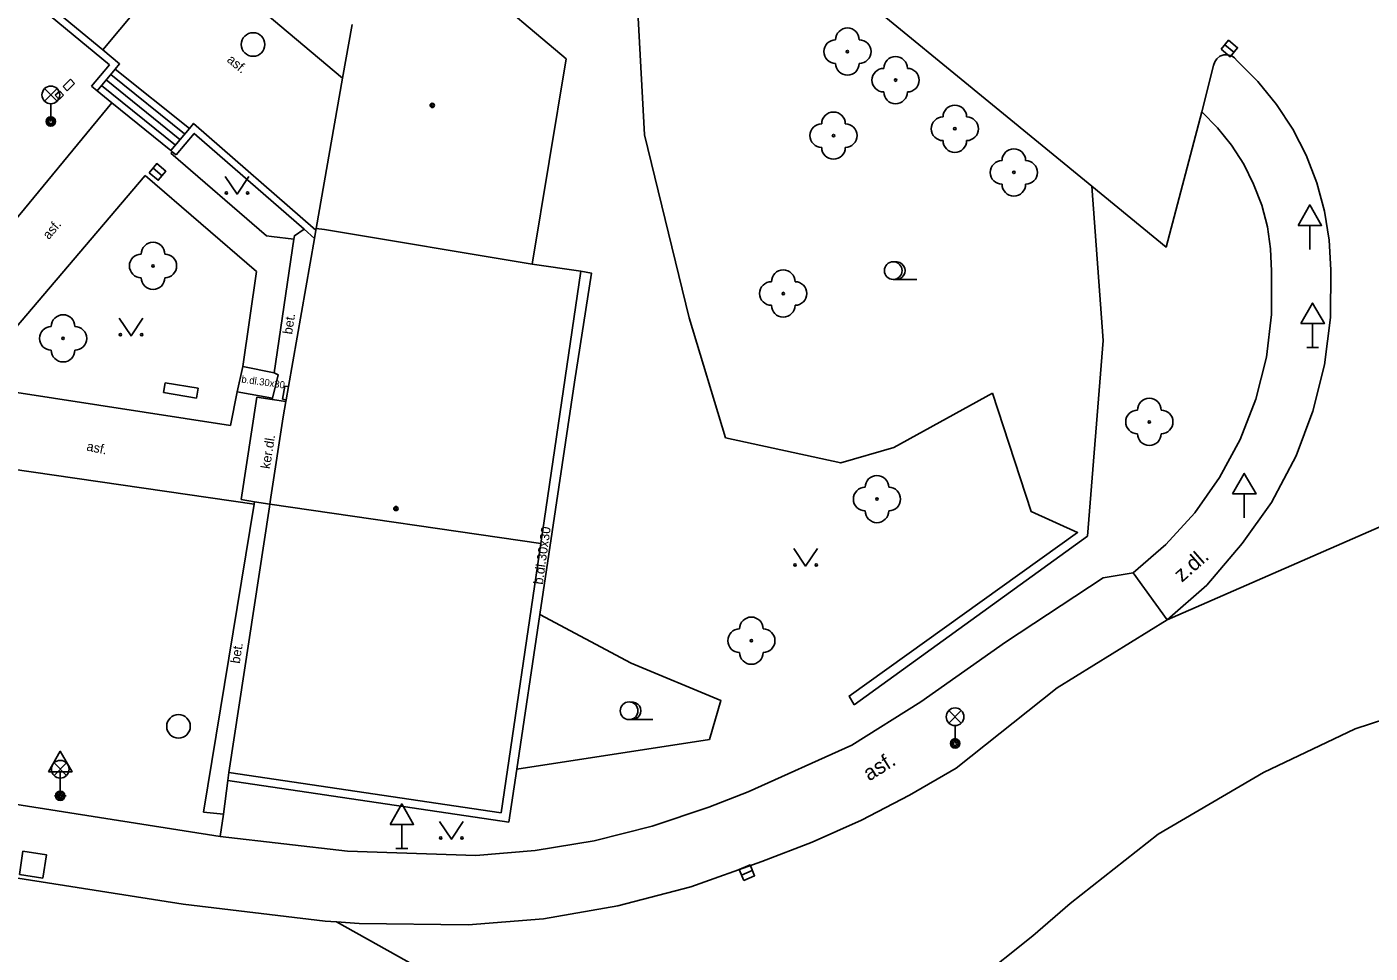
# Model space of a CAD drawing. Extents: x -598932 to -598196, y -1162207 to -1161504.
# Drawn here: x -598441.5 to -598384.6, y -1162005.3 to -1161966.1 of the extents above; entities that cross this region are included whole.
import ezdxf

# ---------------------------------------------------------------- set-up
doc = ezdxf.new("R2010")
doc.units = 0
for name, color, linetype in [('Level 22', 7, 'Continuous'), ('Level 26', 7, 'Continuous'), ('Level 27', 7, 'Continuous'), ('Level 33', 7, 'Continuous'), ('Level 34', 7, 'Continuous'), ('Level 36', 7, 'Continuous'), ('Level 39', 7, 'Continuous'), ('silnoproud - povrch.  znaky a  RIS  skut. velikost', 7, 'Continuous'), ('specificka linie pasportu komunikaci', 7, 'Continuous'), ('TM - budovy zdene_ betonove - NP', 7, 'Continuous'), ('TM - budovy zdene_ betonove - VN', 7, 'Continuous'), ('TM - budovy zdene_ betonove - VP', 7, 'Continuous'), ('TM - chodniky - VP', 7, 'Continuous'), ('TM - hranice souvisleho porostu (skupiny stromu_ kere)', 7, 'Continuous'), ('TM - komunikace - VP', 7, 'Continuous'), ('TM - letecke snimky - pomocna linie', 7, 'Continuous'), ('TM - podezdivka plotu - VP', 7, 'Continuous'), ('TM - pomocna konstrukcna linie', 7, 'Continuous'), ('TM - popis povrchu', 7, 'Continuous'), ('TM - rozhrani mezi zpev. plochami mezi sebou - VP', 7, 'Continuous'), ('TM - rozhrani ploch obecne - VP', 7, 'Continuous'), ('TM - schody - VP', 7, 'Continuous'), ('TM - vstup do budovy - nerozlisene', 7, 'Continuous'), ('TM - zed operna - VP', 7, 'Continuous')]:
    doc.layers.add(name, color=color, linetype=linetype)

msp = doc.modelspace()

# ---------------------------------------------------------------- linework, layer by layer
at = {"layer": 'Level 22'}
for centre in [(-598406.76, -1161967.12), (-598404.72, -1161968.33), (-598407.35, -1161970.68), (-598402.21, -1161970.39), (-598399.71, -1161972.24), (-598436.18, -1161976.2), (-598409.48, -1161977.37), (-598439.99, -1161979.27), (-598393.97, -1161982.81), (-598405.51, -1161986.08), (-598410.83, -1161992.08)]:
    msp.add_circle(centre, 0.05, dxfattribs=at)
for centre, start, end in [((-598406.76, -1161966.62), 0, 180), ((-598407.26, -1161967.12), 90, 270), ((-598406.26, -1161967.12), 270, 90), ((-598406.76, -1161967.62), 180, 0), ((-598405.22, -1161968.33), 90, 270), ((-598404.72, -1161967.83), 0, 180), ((-598404.22, -1161968.33), 270, 90), ((-598404.72, -1161968.83), 180, 0), ((-598402.21, -1161969.89), 0, 180), ((-598407.35, -1161970.18), 0, 180), ((-598402.71, -1161970.39), 90, 270), ((-598401.71, -1161970.39), 270, 90), ((-598407.85, -1161970.68), 90, 270), ((-598406.85, -1161970.68), 270, 90), ((-598407.35, -1161971.18), 180, 0), ((-598402.21, -1161970.89), 180, 0), ((-598399.71, -1161971.74), 0, 180), ((-598400.21, -1161972.24), 90, 270), ((-598399.21, -1161972.24), 270, 90), ((-598399.71, -1161972.74), 180, 0), ((-598436.18, -1161975.7), 0, 180), ((-598436.68, -1161976.2), 90, 270), ((-598435.68, -1161976.2), 270, 90), ((-598409.48, -1161976.87), 0, 180), ((-598436.18, -1161976.7), 180, 0), ((-598409.98, -1161977.37), 90, 270), ((-598408.98, -1161977.37), 270, 90), ((-598409.48, -1161977.87), 180, 0), ((-598439.99, -1161978.77), 0, 180), ((-598440.49, -1161979.27), 90, 270), ((-598439.49, -1161979.27), 270, 90), ((-598439.99, -1161979.77), 180, 0), ((-598393.97, -1161982.31), 0, 180), ((-598394.47, -1161982.81), 90, 270), ((-598393.47, -1161982.81), 270, 90), ((-598393.97, -1161983.31), 180, 0), ((-598405.51, -1161985.58), 0, 180), ((-598406.01, -1161986.08), 90, 270), ((-598405.01, -1161986.08), 270, 90), ((-598405.51, -1161986.58), 180, 0), ((-598410.83, -1161991.58), 0, 180), ((-598411.33, -1161992.08), 90, 270), ((-598410.33, -1161992.08), 270, 90), ((-598410.83, -1161992.58), 180, 0)]:
    msp.add_arc(centre, 0.5, start, end, dxfattribs=at)
at = {"layer": 'Level 26'}
msp.add_lwpolyline([(-598441.84, -1162001.989), (-598440.851, -1162002.14), (-598440.7, -1162001.151), (-598441.689, -1162001)], close=True, dxfattribs=at)
at = {"layer": 'Level 27'}
for p, q in [((-598390.773, -1161966.831), (-598390.387, -1161967.149)), ((-598436.181, -1161972.059), (-598435.799, -1161972.381)), ((-598411.25, -1162002.008), (-598410.79, -1162001.812))]:
    msp.add_line(p, q, dxfattribs=at)
for points in [[(-598390.932, -1161967.023), (-598390.547, -1161967.342), (-598390.228, -1161966.957), (-598390.613, -1161966.638)], [(-598436.342, -1161972.251), (-598435.959, -1161972.572), (-598435.638, -1161972.189), (-598436.021, -1161971.868)], [(-598411.152, -1162002.238), (-598410.692, -1162002.042), (-598410.888, -1162001.582), (-598411.348, -1162001.778)]]:
    msp.add_lwpolyline(points, close=True, dxfattribs=at)
for centre in [(-598431.94, -1161966.82), (-598435.1, -1161995.71)]:
    msp.add_circle(centre, 0.5, dxfattribs=at)
at = {"layer": 'Level 33'}
for p, q in [((-598440.775, -1161969.22), (-598440.245, -1161968.69)), ((-598440.775, -1161968.69), (-598440.245, -1161969.22)), ((-598440.51, -1161969.33), (-598440.51, -1161970.08)), ((-598402.465, -1161995.57), (-598401.935, -1161995.04)), ((-598402.465, -1161995.04), (-598401.935, -1161995.57)), ((-598402.2, -1161995.68), (-598402.2, -1161996.43)), ((-598440.375, -1161997.79), (-598439.845, -1161997.26)), ((-598440.375, -1161997.26), (-598439.845, -1161997.79)), ((-598440.11, -1161997.9), (-598440.11, -1161998.65))]:
    msp.add_line(p, q, dxfattribs=at)
for centre, radius in [((-598440.51, -1161968.955), 0.375), ((-598440.51, -1161970.08), 0.2), ((-598440.51, -1161970.08), 0.145), ((-598440.51, -1161970.08), 0.0876), ((-598402.2, -1161995.305), 0.375), ((-598402.2, -1161996.43), 0.2), ((-598402.2, -1161996.43), 0.145), ((-598402.2, -1161996.43), 0.0876), ((-598440.11, -1161997.525), 0.375), ((-598440.11, -1161998.65), 0.2), ((-598440.11, -1161998.65), 0.145), ((-598440.11, -1161998.65), 0.0876)]:
    msp.add_circle(centre, radius, dxfattribs=at)
at = {"layer": 'Level 34'}
for p, q in [((-598387.17, -1161974.482), (-598387.17, -1161975.5)), ((-598387.05, -1161978.642), (-598387.05, -1161979.66)), ((-598387.3, -1161979.66), (-598386.8, -1161979.66)), ((-598389.95, -1161985.862), (-598389.95, -1161986.88)), ((-598440.11, -1161997.632), (-598440.11, -1161998.65)), ((-598440.36, -1161998.65), (-598439.86, -1161998.65)), ((-598425.64, -1161999.862), (-598425.64, -1162000.88)), ((-598425.89, -1162000.88), (-598425.39, -1162000.88))]:
    msp.add_line(p, q, dxfattribs=at)
for points in [[(-598387.67, -1161974.482), (-598386.67, -1161974.482), (-598387.17, -1161973.616)], [(-598387.55, -1161978.642), (-598386.55, -1161978.642), (-598387.05, -1161977.776)], [(-598390.45, -1161985.862), (-598389.45, -1161985.862), (-598389.95, -1161984.996)], [(-598440.61, -1161997.632), (-598439.61, -1161997.632), (-598440.11, -1161996.766)], [(-598426.14, -1161999.862), (-598425.14, -1161999.862), (-598425.64, -1161998.996)]]:
    msp.add_lwpolyline(points, close=True, dxfattribs=at)
at = {"layer": 'Level 36'}
for p, q in [((-598404.82, -1161976.775), (-598403.82, -1161976.775)), ((-598416.01, -1161995.425), (-598415.01, -1161995.425))]:
    msp.add_line(p, q, dxfattribs=at)
for points in [[(-598433.12, -1161972.41), (-598432.62, -1161973.16), (-598432.12, -1161972.41)], [(-598437.61, -1161978.42), (-598437.11, -1161979.17), (-598436.61, -1161978.42)], [(-598409.03, -1161988.17), (-598408.53, -1161988.92), (-598408.03, -1161988.17)], [(-598424.04, -1161999.74), (-598423.54, -1162000.49), (-598423.04, -1161999.74)]]:
    msp.add_lwpolyline(points, dxfattribs=at)
for centre, radius in [((-598433.07, -1161973.11), 0.05), ((-598432.171, -1161973.11), 0.05), ((-598404.82, -1161976.4), 0.375), ((-598437.56, -1161979.12), 0.05), ((-598436.661, -1161979.12), 0.05), ((-598408.98, -1161988.87), 0.05), ((-598408.081, -1161988.87), 0.05), ((-598416.01, -1161995.05), 0.375), ((-598423.99, -1162000.44), 0.05), ((-598423.091, -1162000.44), 0.05)]:
    msp.add_circle(centre, radius, dxfattribs=at)
for centre in [(-598404.695, -1161976.4), (-598415.885, -1161995.05)]:
    msp.add_arc(centre, 0.375, 260.4059, 99.5941, dxfattribs=at)
at = {"layer": 'Level 39'}
for centre, radius in [((-598424.35, -1161969.4), 0.09), ((-598424.35, -1161969.4), 0.0398), ((-598425.89, -1161986.48), 0.09), ((-598425.89, -1161986.48), 0.0398)]:
    msp.add_circle(centre, radius, dxfattribs=at)
at = {"layer": 'silnoproud - povrch.  znaky a  RIS  skut. velikost'}
for points in [[(-598439.99, -1161968.6), (-598439.67, -1161968.29)], [(-598439.67, -1161968.29), (-598439.5, -1161968.47)], [(-598440.32, -1161968.97), (-598440.13, -1161968.8)], [(-598440.16, -1161969.15), (-598440.32, -1161968.97)], [(-598439.97, -1161968.97), (-598440.16, -1161969.15)], [(-598440.13, -1161968.8), (-598439.97, -1161968.97)], [(-598439.82, -1161968.78), (-598439.99, -1161968.6)], [(-598439.5, -1161968.47), (-598439.82, -1161968.78)], [(-598435.66, -1161981.15), (-598435.73, -1161981.57)], [(-598434.27, -1161981.38), (-598435.66, -1161981.15)], [(-598434.34, -1161981.8), (-598434.27, -1161981.38)], [(-598430.6, -1161981.29), (-598430.69, -1161981.85)], [(-598430.44, -1161981.31), (-598430.6, -1161981.29)], [(-598435.73, -1161981.57), (-598434.34, -1161981.8)], [(-598430.69, -1161981.85), (-598430.54, -1161981.87)]]:
    msp.add_lwpolyline(points, dxfattribs=at)
at = {"layer": 'specificka linie pasportu komunikaci'}
for points in [[(-598393.22, -1161991.2), (-598383.224, -1161986.832)], [(-598411.23, -1162013.6), (-598428.408, -1162003.993)]]:
    msp.add_lwpolyline(points, dxfattribs=at)
at = {"layer": 'TM - budovy zdene_ betonove - NP'}
msp.add_lwpolyline([(-598428.15, -1161968.25), (-598427.75, -1161965.97)], dxfattribs=at)
at = {"layer": 'TM - budovy zdene_ betonove - VN'}
msp.add_lwpolyline([(-598434.7, -1161962.73), (-598428.15, -1161968.25)], dxfattribs=at)
at = {"layer": 'TM - budovy zdene_ betonove - VP'}
for points in [[(-598426.86, -1161960.52), (-598426.39, -1161960.92), (-598418.67, -1161967.42)], [(-598418.67, -1161967.42), (-598420.12, -1161976.12)], [(-598430.67, -1161982.59), (-598430.55, -1161981.95), (-598430.54, -1161981.87), (-598430.44, -1161981.31), (-598429.34, -1161975.04), (-598429.28, -1161974.69), (-598429.27, -1161974.61), (-598428.15, -1161968.25)], [(-598429.27, -1161974.61), (-598428.92, -1161974.66)], [(-598420.12, -1161976.12), (-598428.92, -1161974.66)], [(-598418.05, -1161976.42), (-598419.75, -1161987.96), (-598421.43, -1161999.38)], [(-598420.12, -1161976.12), (-598418.05, -1161976.42)], [(-598431.19, -1161986), (-598430.67, -1161982.59)], [(-598432.97, -1161997.67), (-598431.25, -1161986.41), (-598431.23, -1161986.29), (-598431.19, -1161986)], [(-598421.43, -1161999.38), (-598432.97, -1161997.67)]]:
    msp.add_lwpolyline(points, dxfattribs=at)
at = {"layer": 'TM - chodniky - VP'}
for points in [[(-598438.55, -1161968.78), (-598437.92, -1161969.29)], [(-598447.06, -1161980.37), (-598437.92, -1161969.29)], [(-598391.75, -1161969.67), (-598391.08, -1161970.35), (-598390.49, -1161971.09), (-598389.97, -1161971.89), (-598389.55, -1161972.73), (-598389.21, -1161973.62), (-598388.97, -1161974.54), (-598388.83, -1161975.48), (-598388.79, -1161976.43)], [(-598435.37, -1161971.36), (-598435.43, -1161971.43)], [(-598430.22, -1161975.07), (-598431.16, -1161974.96), (-598431.37, -1161974.92), (-598435.43, -1161971.43)], [(-598444.07, -1161981.24), (-598436.51, -1161972.37)], [(-598436.51, -1161972.37), (-598431.79, -1161976.44)], [(-598430.22, -1161975.07), (-598430.19, -1161974.92), (-598429.78, -1161974.65)], [(-598432.9, -1161982.96), (-598432.61, -1161981.54), (-598432.38, -1161980.46), (-598431.79, -1161976.44)], [(-598394.66, -1161989.2), (-598393.27, -1161988.01), (-598392.04, -1161986.66), (-598390.99, -1161985.16), (-598390.12, -1161983.55), (-598389.46, -1161981.85), (-598389.01, -1161980.07), (-598388.79, -1161978.26), (-598388.79, -1161976.43)], [(-598432.9, -1161982.96), (-598444.07, -1161981.24)], [(-598433.33, -1162000.37), (-598456.85, -1161996.68), (-598446.03, -1161984.25)], [(-598431.9, -1161986.3), (-598446.03, -1161984.25)], [(-598394.66, -1161989.2), (-598395.93, -1161989.42), (-598400.07, -1161992.14), (-598403.65, -1161994.67), (-598406.57, -1161996.5), (-598410.97, -1161998.48), (-598412.63, -1161999.13)], [(-598433.33, -1162000.37), (-598433.2, -1161999.43), (-598433.01, -1161998), (-598432.97, -1161997.67)], [(-598433.33, -1162000.37), (-598427.94, -1162001), (-598422.51, -1162001.18), (-598419.99, -1162000.97), (-598417.49, -1162000.56), (-598415.03, -1161999.94), (-598412.63, -1161999.13)]]:
    msp.add_lwpolyline(points, dxfattribs=at)
at = {"layer": 'TM - hranice souvisleho porostu (skupiny stromu_ kere)'}
for points in [[(-598395.92, -1161979.36), (-598396.59, -1161987.65)], [(-598406.48, -1161994.8), (-598406.69, -1161994.43), (-598397.01, -1161987.5), (-598398.98, -1161986.6), (-598400.62, -1161981.59)], [(-598406.48, -1161994.8), (-598396.59, -1161987.65)], [(-598419.79, -1161990.97), (-598415.92, -1161993.03), (-598412.12, -1161994.61), (-598412.61, -1161996.26), (-598420.77, -1161997.53)]]:
    msp.add_lwpolyline(points, dxfattribs=at)
at = {"layer": 'TM - komunikace - VP'}
for points in [[(-598416.41, -1161947.39), (-598414.06, -1161949.25), (-598410.52, -1161961.26), (-598396.41, -1161972.82), (-598393.26, -1161975.4), (-598391.75, -1161969.67)], [(-598391.25, -1161967.71), (-598391.2, -1161967.55), (-598391.11, -1161967.42), (-598390.98, -1161967.31), (-598390.82, -1161967.26), (-598390.66, -1161967.25), (-598390.5, -1161967.29), (-598390.36, -1161967.38), (-598390.25, -1161967.51)], [(-598391.75, -1161969.67), (-598391.25, -1161967.71)], [(-598386.28, -1161976.36), (-598386.35, -1161975.11), (-598386.55, -1161973.88), (-598386.87, -1161972.68), (-598387.32, -1161971.51), (-598387.89, -1161970.4), (-598388.58, -1161969.36), (-598389.37, -1161968.39), (-598390.25, -1161967.51)], [(-598393.22, -1161991.2), (-598391.54, -1161989.73), (-598390.03, -1161987.96), (-598388.79, -1161986.23), (-598387.75, -1161984.25), (-598387.04, -1161982.36), (-598386.55, -1161980.39), (-598386.3, -1161978.38), (-598386.28, -1161976.36)], [(-598402.16, -1161997.48), (-598397.87, -1161994.08), (-598393.22, -1161991.2)], [(-598397.32, -1162003.22), (-598393.6, -1162000.28), (-598389.13, -1161997.67), (-598385.25, -1161995.81), (-598380.74, -1161994.34), (-598378.9, -1161993.91), (-598376.09, -1161993.41), (-598370, -1161993.04), (-598366.62, -1161993.2), (-598361.93, -1161993.93)], [(-598422.83, -1162004.12), (-598419.64, -1162003.86), (-598416.49, -1162003.32), (-598413.39, -1162002.51), (-598410.38, -1162001.43), (-598408.25, -1162000.61), (-598406.16, -1161999.68), (-598404.13, -1161998.63), (-598402.16, -1161997.48)], [(-598434.91, -1162003.24), (-598462.4, -1161998.92)], [(-598434.91, -1162003.24), (-598428.89, -1162003.96), (-598428.408, -1162003.993), (-598427.44, -1162004.06), (-598422.83, -1162004.12)], [(-598411.14, -1162012.49), (-598408.36, -1162011.05), (-598405.66, -1162009.47), (-598403.91, -1162008.34), (-598401.35, -1162006.53), (-598398.9, -1162004.59), (-598397.32, -1162003.22)]]:
    msp.add_lwpolyline(points, dxfattribs=at)
at = {"layer": 'TM - letecke snimky - pomocna linie'}
for points in [[(-598400.62, -1161981.59), (-598404.79, -1161983.89), (-598407.04, -1161984.55), (-598411.92, -1161983.48), (-598413.46, -1161978.4), (-598415.36, -1161970.65), (-598416.13, -1161956.29), (-598414.63, -1161950.52), (-598414.06, -1161949.25)], [(-598395.92, -1161979.36), (-598396.41, -1161972.82)]]:
    msp.add_lwpolyline(points, dxfattribs=at)
at = {"layer": 'TM - podezdivka plotu - VP'}
for points in [[(-598449.71, -1161957.58), (-598443.11, -1161963.09), (-598438.31, -1161967.05), (-598437.6, -1161967.64), (-598437.78, -1161967.86), (-598438.55, -1161968.78)], [(-598438.78, -1161968.59), (-598438.55, -1161968.78)], [(-598435.2, -1161971.5), (-598435.37, -1161971.36), (-598435.43, -1161971.31), (-598434.64, -1161970.38), (-598434.46, -1161970.16), (-598429.28, -1161974.69)]]:
    msp.add_lwpolyline(points, dxfattribs=at)
at = {"layer": 'TM - pomocna konstrukcna linie'}
for points in [[(-598418.05, -1161976.42), (-598417.6, -1161976.51), (-598418.33, -1161981.13)], [(-598431.23, -1161986.29), (-598419.75, -1161987.96)]]:
    msp.add_lwpolyline(points, dxfattribs=at)
at = {"layer": 'TM - rozhrani mezi zpev. plochami mezi sebou - VP'}
for points in [[(-598434.7, -1161962.73), (-598438.31, -1161967.05)], [(-598431.13, -1161981.86), (-598431.12, -1161981.81), (-598430.88, -1161980.81), (-598431.05, -1161980.73), (-598430.22, -1161975.07)], [(-598432.38, -1161980.46), (-598431.05, -1161980.73)], [(-598431.12, -1161981.81), (-598432.61, -1161981.54)]]:
    msp.add_lwpolyline(points, dxfattribs=at)
at = {"layer": 'TM - rozhrani ploch obecne - VP'}
for points in [[(-598437.78, -1161967.86), (-598434.64, -1161970.38)], [(-598437.92, -1161969.29), (-598435.43, -1161971.31)], [(-598421.1, -1161999.77), (-598420.77, -1161997.53), (-598419.79, -1161990.97), (-598418.33, -1161981.13)], [(-598432.44, -1161986.1), (-598431.78, -1161981.76)], [(-598431.78, -1161981.76), (-598431.13, -1161981.86), (-598430.55, -1161981.95)], [(-598432.44, -1161986.1), (-598431.88, -1161986.19), (-598431.23, -1161986.29)], [(-598431.9, -1161986.3), (-598434.04, -1161999.34)], [(-598431.88, -1161986.19), (-598431.9, -1161986.3)], [(-598393.22, -1161991.2), (-598394.66, -1161989.2)], [(-598433.01, -1161998), (-598421.1, -1161999.77)], [(-598434.04, -1161999.34), (-598433.2, -1161999.43)]]:
    msp.add_lwpolyline(points, dxfattribs=at)
at = {"layer": 'TM - schody - VP'}
for points in [[(-598435.04, -1161970.84), (-598438.17, -1161968.32)], [(-598437.97, -1161968.09), (-598434.84, -1161970.61)], [(-598438.36, -1161968.55), (-598435.23, -1161971.08)]]:
    msp.add_lwpolyline(points, dxfattribs=at)
at = {"layer": 'TM - vstup do budovy - nerozlisene'}
msp.add_lwpolyline([(-598431.19, -1161986), (-598430.67, -1161982.59)], dxfattribs=at)
at = {"layer": 'TM - zed operna - VP'}
for points in [[(-598438.02, -1161967.68), (-598443.3, -1161963.32), (-598449.89, -1161957.82)], [(-598438.78, -1161968.59), (-598438.02, -1161967.68)], [(-598435.2, -1161971.5), (-598434.43, -1161970.59), (-598429.78, -1161974.65), (-598429.34, -1161975.04)]]:
    msp.add_lwpolyline(points, dxfattribs=at)

# ---------------------------------------------------------------- texts
at = {"layer": 'TM - popis povrchu'}
for s, height, rotation, p in [('asf.', 0.4, 320.47, (-598433.08, -1161967.52)), ('asf.', 0.4, 50.308, (-598440.59, -1161975.11)), ('bet.', 0.4, 81.2939, (-598430.29, -1161979.12)), ('b.dl.30x30', 0.3, 352, (-598432.45, -1161981.14)), ('asf.', 0.4, 348.3524, (-598439.02, -1161984.02)), ('ker.dl.', 0.4, 81, (-598431.23, -1161984.82)), ('b.dl.30x30', 0.4, 82, (-598419.67, -1161989.72)), ('z.dl.', 0.65, 41.1859, (-598392.59, -1161989.63)), ('bet.', 0.4, 81, (-598432.51, -1161993.07)), ('asf.', 0.65, 32.08, (-598405.84, -1161998.05))]:
    msp.add_text(s, height=height, rotation=rotation, dxfattribs=at).set_placement(p)

doc.saveas('drawing.dxf')
